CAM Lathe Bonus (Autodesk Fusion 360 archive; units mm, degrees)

design "CAM Lathe Bonus" references "Generic 3 Jaw Chuck"
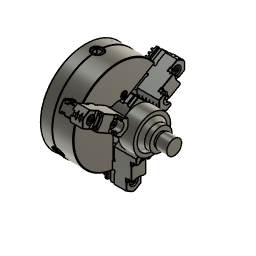
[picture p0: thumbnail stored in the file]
sketch "Sketch1" plane through (0, 0, 0) normal (0, 1, 0) x axis (1, 0, 0)
  line L1 (63.5, 0) -> (0, 0)
  line L2 (38.1, 0) -> (0, 0)
  line L3 (38.1, -6.35) -> (38.1, 0)
  line L4 (60.325, -6.35) -> (38.1, -6.35)
  line L5 (63.5, -9.525) -> (60.325, -6.35)
  line L6 (63.5, -12.7) -> (63.5, -9.525)
  line L7 (44.45, -12.7) -> (63.5, -12.7)
  line L8 (44.45, -11.43) -> (44.45, -12.7)
  line L9 (40.4812, -11.43) -> (44.45, -11.43)
  line L10 (40.4812, -19.05) -> (40.4812, -11.43)
  line L11 (31.75, -19.05) -> (40.4812, -19.05)
  line L12 (25.4, -25.4) -> (31.75, -19.05)
  line L13 (25.4, -31.75) -> (25.4, -25.4)
  line L14 (0, -31.75) -> (25.4, -31.75)
  line L15 (0, 0) -> (0, -31.75)
  line L16 (63.5, 0) -> (63.5, -9.525)
  point P1 (0, 0)
  point P2 (0, 0)
  point P4 (0, 0)
  point P5 (38.1, 0)
  point P18 (0, 0)
  point P3 (63.5, 0)
  point P7 (60.325, -6.35)
  point P8 (63.5, -9.525)
  point P10 (44.45, -12.7)
  point P11 (44.45, -11.43)
  point P9 (63.5, -12.7)
  point P14 (31.75, -19.05)
  point P15 (25.4, -25.4)
  point P16 (25.4, -31.75)
  point P17 (0, -31.75)
  coincident P1 P2
  horizontal L1
  coincident P1 P4
  coincident L1 P5
  parallel L1 L2
  perpendicular L2 L3
  perpendicular L3 L4
  perpendicular L4 L6
  perpendicular L6 L7
  perpendicular L7 L8
  perpendicular L8 L9
  perpendicular L9 L10
  perpendicular L10 L11
  perpendicular L11 L13
  perpendicular L13 L14
  coincident P1 P18
  perpendicular L1 L15
  coincident P3 L6
  dimension "d1" distance P2 P3 = 63.5
  dimension "d2" angle L4 L5 = 45
  dimension "d3" distance P7 P8 = 3.175
  dimension "d4" = 12.7
  dimension "d5" distance L3 L6 = 25.4
  dimension "d7" distance L8 L10 = 3.9688
  dimension "d8" distance P10 P11 = 1.27
  dimension "d9" distance P9 P10 = 19.05
  dimension "d10" angle L11 L12 = 45
  dimension "d11" distance P14 P15 = 6.35
  dimension "d12" = 63.5
  dimension "d13" distance P16 P17 = 25.4
  dimension "d15" = 25.4
  dimension "d16" = 38.1
revolve "Revolve1" sketch "Sketch1" AlongAngle 360 bodies "Extra Stock"
component_insert "Component Insert"
as_built_joint "As-built1"
joint "Assemble1" alignAngle -90 alignOffsetX 0 alignOffsetY 0 alignOffsetZ 31.75
copy_paste_bodies "CopyPasteBodies1"
offset_faces "OffsetFaces1" distance -17.78
fillet "Fillet1" radius 0.3969 (= "( 0.03125 / 2 ) * 1 in")
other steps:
base_feature "Base Feature" bodies "Real Model"
joint_origin "JointOrigin4"
named bodies: "Extra Stock", "Real Model"

design "Generic 3 Jaw Chuck"
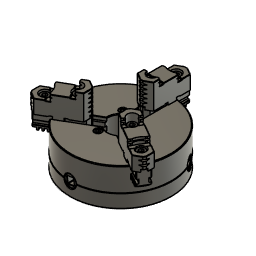
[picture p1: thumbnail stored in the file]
base_feature "Base Feature1"
base_feature "Base Feature1"
base_feature "Base Feature1"
base_feature "Base Feature1"
base_feature "Base Feature1"
base_feature "Base Feature1"
base_feature "Base Feature1"
base_feature "Base Feature1"
base_feature "Base Feature1"
base_feature "Base Feature1"
as_built_joint "As-built1"
as_built_joint "As-built1"
as_built_joint "As-built1"
as_built_joint "As-built2"
as_built_joint "As-built3" OffsetX 0 OffsetY 0 OffsetZ 0 AngleZ 0
step "C-Pattern" TotalAngle 360
as_built_joint "As-built4" OffsetX 0 OffsetY 0 OffsetZ 0 AngleZ 0
as_built_joint "As-built5" OffsetX 0 OffsetY 0 OffsetZ 0 AngleZ 0
as_built_joint "As-built6" OffsetX 0 OffsetY 0 OffsetZ 0 AngleZ 0
motion_link "MotionLink1" Value1 1 Value2 5.15
motion_link "MotionLink2" Value1 1 Value2 5.15
motion_link "MotionLink3" Value1 1 Value2 5.15
step "00000000-0000-0000-0000-000000000000" TotalAngle 360
as_built_joint "As-built2" OffsetX 0 OffsetY 0 OffsetZ 0 AngleZ 0 SlideMinimum -63.5 SlideMaximum 0
as_built_joint "As-built3" OffsetX 0 OffsetY 0 OffsetZ 0 AngleZ 0
as_built_joint "As-built4" OffsetX 0 OffsetY 0 OffsetZ 0 AngleZ 0
motion_link "MotionLink1" Value1 25.4 Value2 25.4
motion_link "MotionLink2" Value1 25.4 Value2 25.4
motion_link "MotionLink3" Value1 1440 Value2 25.4
sketch "Sketch1" plane through (0, 36, 0) normal (0, 1, 0) x axis (-1, 0, 0)
  line L1 (9.5, -75.9072) -> (9.5, -18.7283)
  line L2 (9.5005, -75.9078) -> (9.5, -75.9072)
  line L3 (70.4876, 29.7264) -> (70.4883, 29.7262)
  line L4 (20.9692, 1.1369) -> (70.4876, 29.7264)
  arc A1 centre (0, 0) radius 21 clockwise from (20.9692, 1.1369) to (9.5, -18.7283)
  arc A2 centre (0, 0) radius 76.5 clockwise from (70.4883, 29.7262) to (9.5005, -75.9078)
  circle C1 centre (17.3553, -20.6832) radius 5.5
  circle C2 centre (0, 0) radius 31.75
  concentric A1 C2
  dimension "d141" diameter C2 = 63.5
position "Position1"
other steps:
create_component "CreateComponent1"
create_component "CreateComponent1"
create_component "CreateComponent2"
create_component "CreateComponent3"
create_component "CreateComponent4"
create_component "CreateComponent5"
create_component "CreateComponent6"
create_component "CreateComponent7"
create_component "CreateComponent2"
create_component "CreateComponent1"
create_component "CreateComponent2"
create_component "CreateComponent3"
